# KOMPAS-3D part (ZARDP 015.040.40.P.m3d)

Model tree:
1. Плоскость XY
2. Плоскость ZX
3. Плоскость ZY
4. Ось X
5. Ось Y
6. Ось Z
7. Начало координат
8. Смещенная плоскость:2
     Расстояние = 60
9. Булева операция:1
10. Булева операция:2
